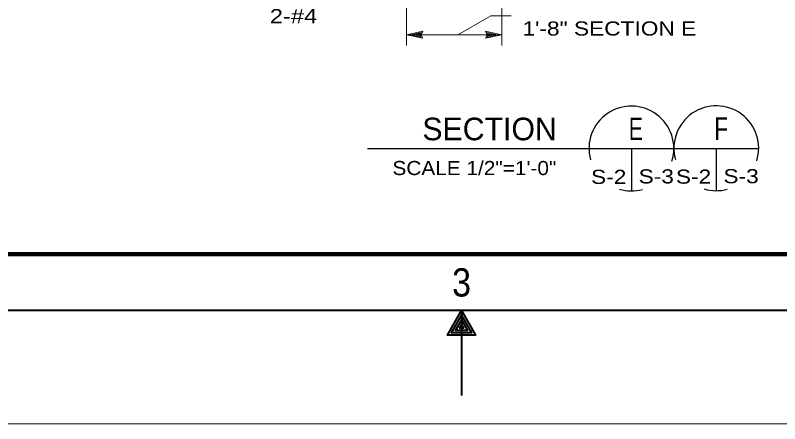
# Model space of a CAD drawing. Extents: x -28.1 to 13.9, y -16.1 to 13.9.
# Drawn here: x -11.09 to -4.33, y -16.13 to -12.51 of the extents above; entities that cross this region are included whole.
import ezdxf
from ezdxf.enums import TextEntityAlignment as Align

# ---------------------------------------------------------------- set-up
doc = ezdxf.new("R2010")
doc.units = 0
doc.header["$LTSCALE"] = 0.05
doc.layers.add('1', color=7, linetype='Continuous', lineweight=13)

msp = doc.modelspace()

# ---------------------------------------------------------------- linework, layer by layer
at = {"layer": '1'}
for p, q in [((-7.62904, -12.32831), (-7.62904, -12.78131)), ((-6.78704, -12.32831), (-6.78704, -12.78131)), ((-6.88404, -12.51931), (-7.17604, -12.68731)), ((-6.88404, -12.51931), (-6.70504, -12.51931)), ((-7.62904, -12.68731), (-7.48504, -12.65631)), ((-7.62904, -12.68731), (-6.78704, -12.68731)), ((-7.62904, -12.68731), (-7.48504, -12.71831)), ((-7.59204, -12.68731), (-7.49804, -12.66731)), ((-7.59204, -12.68731), (-7.49804, -12.70731)), ((-7.55604, -12.68731), (-7.51104, -12.67731)), ((-7.55604, -12.68731), (-7.51104, -12.69631)), ((-7.51104, -12.67731), (-7.51504, -12.68731)), ((-7.51504, -12.68731), (-7.51104, -12.69631)), ((-7.49804, -12.66731), (-7.50704, -12.68731)), ((-7.50704, -12.68731), (-7.49804, -12.70731)), ((-6.78704, -12.68731), (-6.93104, -12.65631)), ((-6.78704, -12.68731), (-6.93104, -12.71831)), ((-6.82404, -12.68731), (-6.91804, -12.66731)), ((-6.90904, -12.68731), (-6.91804, -12.66731)), ((-6.82404, -12.68731), (-6.91804, -12.70731)), ((-6.91804, -12.70731), (-6.90904, -12.68731)), ((-6.86004, -12.68731), (-6.90504, -12.67831)), ((-6.90104, -12.68731), (-6.90504, -12.67831)), ((-6.86004, -12.68731), (-6.90504, -12.69731)), ((-6.90504, -12.69731), (-6.90104, -12.68731)), ((13.85696, -16.12731), (-28.14304, -16.12731))]:
    msp.add_line(p, q, dxfattribs=at)
at = {"layer": '1', "lineweight": 25}
for p, q in [((-7.97504, -13.69331), (-4.51704, -13.69331)), ((-5.64104, -13.69331), (-5.64104, -14.06831)), ((-4.89104, -13.69131), (-4.89104, -14.06631))]:
    msp.add_line(p, q, dxfattribs=at)
at = {"layer": '1', "lineweight": 40}
msp.add_line((-7.14304, -15.12731), (-7.14304, -15.87731), dxfattribs=at)
for points in [[(-27.14304, -15.12731), (-27.14304, 12.87269), (12.85696, 12.87269), (12.85696, -15.12731)], [(-7.14304, -15.12731), (-7.01804, -15.34431), (-7.26804, -15.34431)]]:
    msp.add_lwpolyline(points, close=True, dxfattribs=at)
at = {"layer": '1', "lineweight": 90}
msp.add_lwpolyline([(-25.64304, 12.37269), (12.35696, 12.37269), (12.35696, -14.62731), (-25.64304, -14.62731)], close=True, dxfattribs=at)
at = {"layer": '1'}
for points in [[(-7.48504, -12.65631), (-7.49904, -12.68731), (-7.48504, -12.71831)], [(-6.93104, -12.71831), (-6.91704, -12.68731), (-6.93104, -12.65631)]]:
    msp.add_lwpolyline(points, dxfattribs=at)
at = {"layer": '1', "lineweight": 40}
for points in [[(-7.14204, -15.17031), (-7.05304, -15.32331), (-7.23104, -15.32331), (-7.14304, -15.17131)], [(-7.14304, -15.20931), (-7.09004, -15.30231), (-7.19504, -15.30231), (-7.14104, -15.20931)], [(-7.14304, -15.25231), (-7.12604, -15.28131), (-7.15904, -15.28131), (-7.14404, -15.25531)]]:
    msp.add_lwpolyline(points, dxfattribs=at)
at = {"layer": '1', "lineweight": 25}
for centre, start, end in [((-5.64104, -13.69331), 342.70891, 195.26862), ((-4.89104, -13.69131), 342.70891, 195.26862), ((-5.64104, -13.69331), 253.4742, 284.92162), ((-4.89104, -13.69131), 253.4742, 284.92162)]:
    msp.add_arc(centre, 0.375, start, end, dxfattribs=at)

# ---------------------------------------------------------------- texts
at = {"layer": '1', "width": 1.25}
msp.add_text('2-#4', height=0.125, dxfattribs=at).set_placement((-8.41883, -12.58531), align=Align.RIGHT)
at = {"layer": '1'}
for s, width, p in [('1\'-8" SECTION E', 1.2, (-6.60404, -12.69431)), ('SCALE 1/2"=1\'-0"', 1.1, (-7.75304, -13.92831))]:
    msp.add_text(s, height=0.125, dxfattribs=dict(at, width=width)).set_placement(p)
msp.add_text('SECTION', height=0.2, dxfattribs=at).set_placement((-6.89464, -13.62031), align=Align.CENTER)
for s, height, width, p in [('E', 0.2, 0.7, (-5.6019, -13.61931)), ('F', 0.2, 0.75, (-4.8479, -13.61731)), ('S-2', 0.125, 1.2, (-5.84168, -14.00631)), ('S-3', 0.125, 1.2, (-5.42168, -14.00231)), ('S-2', 0.125, 1.2, (-5.09168, -14.00431)), ('S-3', 0.125, 1.2, (-4.67168, -14.00031)), ('3', 0.25, 0.9, (-7.14222, -15.00231))]:
    msp.add_text(s, height=height, dxfattribs=dict(at, width=width)).set_placement(p, align=Align.CENTER)

doc.saveas('drawing.dxf')
